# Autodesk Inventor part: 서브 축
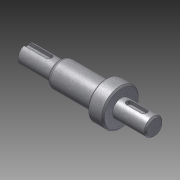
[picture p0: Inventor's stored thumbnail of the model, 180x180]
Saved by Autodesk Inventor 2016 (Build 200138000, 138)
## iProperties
Created: 2016-04
Part Number: 서브 축
Document SubType Name: Modeling
Designer: mdu
Density: 1 g/cm^3
Mass: 19.9624 g
Surface Area: 57.7178 cm^2
Volume: 19.9624 cm^3
Material: 강철, 연강
Appearance: 금속-강(스테인리스, 브러시됨)
Author: mdu
Revision Number: 1
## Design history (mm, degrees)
sketch "스케치1"
  geometry: L1 (-16.331, 0)-(-103.831, 0); L2 (-16.331, 0)-(-16.331, -6); L3 (-16.331, -6)-(-38.831, -6); L4 (-38.831, -12.5)-(-46.5, -12.5); L5 (-46.5, -8.5)-(-79.013, -8.5); L6 (-103.831, -6)-(-103.831, 0); L7 (-46.5, -8.5)-(-46.5, -12.5); L8 (-38.831, -6)-(-38.831, -12.5); L9 (-46.5, 12.249)-(-46.5, -12.249) reference; L10 (-38.831, -17)-(-38.831, 17) reference; L11 (-103.831, -6)-(-80.831, -6); L12 (-80.831, -6)-(-80.831, -7.45); L13 (-80.831, -7.45)-(-79.013, -8.5); 2 further points
  constraints: 23 end point, 6 perpendicular, 2 collinear, 2 parallel, 1 horizontal, 1 midpoint, 1 point on line
  dimensions: "d1" = 12 diameter of L3 L1; "d2" = 25 diameter of L4 L1; "d3" = 17 diameter of L5 L1; "d18" = 22.5 distance of L2.end L3.end; "d20" = 65 distance between parallel lines of L6 L8; "d21" = 7.66872 distance of L4.start L4.end (derived); "d28" = 12 diameter of L11 L1; "d29" = 23 distance of L6.start L11.end; "d30" = 14.9 diameter of L12.end L1; "d32" = 30 deg angle of L5 L13
revolve "회전1" sketch "스케치1" stored, may be unused: angle "d5" = 90 deg
chamfer "모따기1" distance "d6" = 1; stored, may be unused: second distance "d7" = 2, angle "d8" = 45 deg
node "작업 평면1"
sketch "스케치2"
  geometry: L1 (11.25, 5)-(11.25, -5) reference; L2 (-5.75, -2)-(4.25, -2); L3 (4.25, 2)-(-5.75, 2); A1 r 2 centre (4.25, 0) between (4.25, -2) and (4.25, 2); A2 r 2 centre (-5.75, 0) between (-5.75, 2) and (-5.75, -2); 2 further points
  constraints: 4 end point, 4 point on circle, 4 tangent, 2 centre point, 1 horizontal alignment, 1 midpoint, 1 parallel, 1 perpendicular
  dimensions: "d9" = 4 distance between parallel lines of L2 L3; "d10" = 14 dimension on A1 A2; "d11" = 5 distance edge to line of A1 L1
extrude "돌출1" cut sketch "스케치2" distance "d12" = 2.5; taper "d13" = 0 deg
node "작업 평면2"
sketch "스케치3"
  geometry: L1 (-103.831, -5)-(-103.831, 5) reference; L2 (-103.831, 2)-(-87.831, 2); L3 (-87.831, -2)-(-103.831, -2); A1 r 2 centre (-87.831, 0) between (-87.831, -2) and (-87.831, 2); 2 further points
  constraints: 4 end point, 2 perpendicular, 2 point on circle, 2 point on line, 2 tangent, 1 centre point, 1 horizontal alignment, 1 midpoint
  dimensions: "d14" = 4 distance between parallel lines of L3 L2; "d15" = 18 dimension on A1 L1
extrude "돌출2" cut sketch "스케치3" distance "d16" = 2.5; taper "d17" = 0 deg
sketch "스케치4"
  geometry: C1 r 12.5 at (0, 0) reference; 1 further point
extrude "돌출3" join sketch "스케치4" distance "d22" = 3; taper "d23" = 0 deg
chamfer "모따기2" distance "d24" = 1; stored, may be unused: second distance "d25" = 2, angle "d26" = 45 deg
fillet "모깎기1" dims "d34" = 1
fillet "모깎기2" dims "d35" = 2
node "솔리드1"
node "참조4"
node "참조5"
other parameters: "d33" = 6
